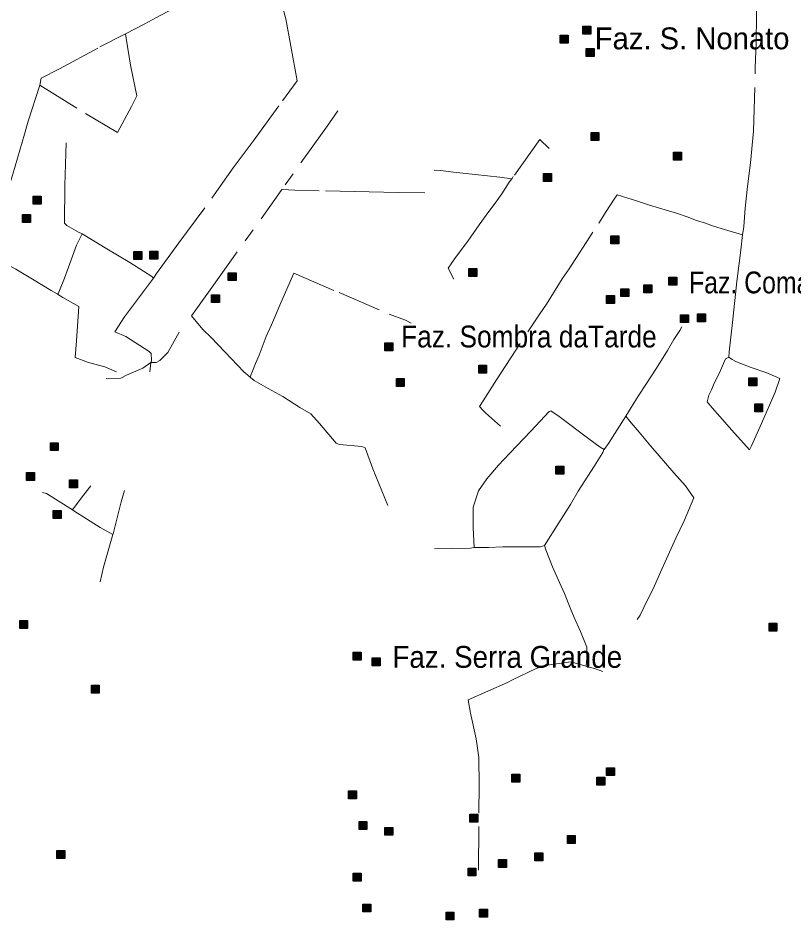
# Model space of a CAD drawing. Extents: x 393.5 to 446.9, y 8064.8 to 8120.4.
# Drawn here: x 419.31 to 425, y 8075.93 to 8082.54 of the extents above; entities that cross this region are included whole.
import ezdxf

# ---------------------------------------------------------------- set-up
doc = ezdxf.new("R2010")
doc.units = 0
doc.header["$LTSCALE"] = 0.064
doc.linetypes.add('DOT_DASHED', pattern=[7.7, 5, -1.2, 0.3, -1.2])
doc.layers.add('2', color=7, linetype='Continuous', lineweight=25)
doc.layers.add('22', color=7, linetype='DOT_DASHED', lineweight=13)
doc.layers.add('61', color=7, linetype='Continuous')

msp = doc.modelspace()

# ---------------------------------------------------------------- hatches: boundary and pattern name
at = {"layer": '2'}
for points in [[(423.4491, 8082.4828), (423.5071, 8082.4828), (423.5071, 8082.4248), (423.4491, 8082.4248)], [(423.2828, 8082.4172), (423.3408, 8082.4172), (423.3408, 8082.3592), (423.2828, 8082.3592)], [(423.473, 8082.319), (423.531, 8082.319), (423.531, 8082.261), (423.473, 8082.261)], [(423.5086, 8081.7029), (423.5666, 8081.7029), (423.5666, 8081.6449), (423.5086, 8081.6449)], [(424.1141, 8081.5584), (424.1721, 8081.5584), (424.1721, 8081.5004), (424.1141, 8081.5004)], [(423.1603, 8081.4031), (423.2183, 8081.4031), (423.2183, 8081.3451), (423.1603, 8081.3451)], [(419.4213, 8081.2362), (419.4793, 8081.2362), (419.4793, 8081.1782), (419.4213, 8081.1782)], [(419.3434, 8081.1027), (419.4014, 8081.1027), (419.4014, 8081.0447), (419.3434, 8081.0447)], [(423.6531, 8080.946), (423.7111, 8080.946), (423.7111, 8080.888), (423.6531, 8080.888)], [(420.1591, 8080.832), (420.2171, 8080.832), (420.2171, 8080.774), (420.1591, 8080.774)], [(420.2759, 8080.834), (420.3339, 8080.834), (420.3339, 8080.776), (420.2759, 8080.776)], [(420.8492, 8080.6762), (420.9072, 8080.6762), (420.9072, 8080.6182), (420.8492, 8080.6182)], [(422.6126, 8080.7057), (422.6706, 8080.7057), (422.6706, 8080.6477), (422.6126, 8080.6477)], [(424.0785, 8080.6427), (424.1365, 8080.6427), (424.1365, 8080.5847), (424.0785, 8080.5847)], [(423.728, 8080.5587), (423.786, 8080.5587), (423.786, 8080.5007), (423.728, 8080.5007)], [(423.8964, 8080.5861), (423.9544, 8080.5861), (423.9544, 8080.5281), (423.8964, 8080.5281)], [(420.7284, 8080.5146), (420.7864, 8080.5146), (420.7864, 8080.4566), (420.7284, 8080.4566)], [(423.6229, 8080.509), (423.6809, 8080.509), (423.6809, 8080.451), (423.6229, 8080.451)], [(424.1646, 8080.368), (424.2226, 8080.368), (424.2226, 8080.31), (424.1646, 8080.31)], [(424.2884, 8080.3752), (424.3464, 8080.3752), (424.3464, 8080.3172), (424.2884, 8080.3172)], [(421.9975, 8080.1619), (422.0555, 8080.1619), (422.0555, 8080.1039), (421.9975, 8080.1039)], [(422.6857, 8079.9989), (422.7437, 8079.9989), (422.7437, 8079.9409), (422.6857, 8079.9409)], [(422.0819, 8079.9007), (422.1399, 8079.9007), (422.1399, 8079.8427), (422.0819, 8079.8427)], [(424.6645, 8079.9048), (424.7225, 8079.9048), (424.7225, 8079.8468), (424.6645, 8079.8468)], [(424.708, 8079.7148), (424.766, 8079.7148), (424.766, 8079.6568), (424.708, 8079.6568)], [(419.5466, 8079.43), (419.6046, 8079.43), (419.6046, 8079.372), (419.5466, 8079.372)], [(419.3715, 8079.2122), (419.4295, 8079.2122), (419.4295, 8079.1542), (419.3715, 8079.1542)], [(423.2513, 8079.2582), (423.3093, 8079.2582), (423.3093, 8079.2002), (423.2513, 8079.2002)], [(419.6865, 8079.1571), (419.7445, 8079.1571), (419.7445, 8079.0991), (419.6865, 8079.0991)], [(419.5675, 8078.9326), (419.6255, 8078.9326), (419.6255, 8078.8746), (419.5675, 8078.8746)], [(419.3221, 8078.1269), (419.3801, 8078.1269), (419.3801, 8078.0689), (419.3221, 8078.0689)], [(424.813, 8078.1068), (424.871, 8078.1068), (424.871, 8078.0488), (424.813, 8078.0488)], [(421.7659, 8077.8952), (421.8239, 8077.8952), (421.8239, 8077.8372), (421.7659, 8077.8372)], [(421.9059, 8077.8528), (421.9639, 8077.8528), (421.9639, 8077.7948), (421.9059, 8077.7948)], [(419.847, 8077.6527), (419.905, 8077.6527), (419.905, 8077.5947), (419.847, 8077.5947)], [(423.6218, 8077.0484), (423.6798, 8077.0484), (423.6798, 8076.9904), (423.6218, 8076.9904)], [(422.9289, 8077.0014), (422.9869, 8077.0014), (422.9869, 8076.9434), (422.9289, 8076.9434)], [(423.5523, 8076.9787), (423.6103, 8076.9787), (423.6103, 8076.9207), (423.5523, 8076.9207)], [(421.7311, 8076.8792), (421.7891, 8076.8792), (421.7891, 8076.8212), (421.7311, 8076.8212)], [(422.6208, 8076.7077), (422.6788, 8076.7077), (422.6788, 8076.6497), (422.6208, 8076.6497)], [(421.8083, 8076.6545), (421.8663, 8076.6545), (421.8663, 8076.5965), (421.8083, 8076.5965)], [(421.9974, 8076.6116), (422.0554, 8076.6116), (422.0554, 8076.5536), (421.9974, 8076.5536)], [(423.3353, 8076.5509), (423.3933, 8076.5509), (423.3933, 8076.4929), (423.3353, 8076.4929)], [(419.5951, 8076.4417), (419.6531, 8076.4417), (419.6531, 8076.3837), (419.5951, 8076.3837)], [(422.8313, 8076.376), (422.8893, 8076.376), (422.8893, 8076.318), (422.8313, 8076.318)], [(423.0973, 8076.4243), (423.1553, 8076.4243), (423.1553, 8076.3663), (423.0973, 8076.3663)], [(422.6071, 8076.3136), (422.6651, 8076.3136), (422.6651, 8076.2556), (422.6071, 8076.2556)], [(421.7665, 8076.2747), (421.8245, 8076.2747), (421.8245, 8076.2167), (421.7665, 8076.2167)], [(421.8367, 8076.0496), (421.8947, 8076.0496), (421.8947, 8075.9916), (421.8367, 8075.9916)], [(422.4463, 8075.9909), (422.5043, 8075.9909), (422.5043, 8075.9329), (422.4463, 8075.9329)], [(422.6915, 8076.0111), (422.7495, 8076.0111), (422.7495, 8075.9531), (422.6915, 8075.9531)]]:
    msp.add_hatch(color=256, dxfattribs=at).paths.add_polyline_path(points)

# ---------------------------------------------------------------- linework, layer by layer
for points in [[(423.4491, 8082.4828), (423.5071, 8082.4828), (423.5071, 8082.4248), (423.4491, 8082.4248)], [(423.2828, 8082.4172), (423.3408, 8082.4172), (423.3408, 8082.3592), (423.2828, 8082.3592)], [(423.473, 8082.319), (423.531, 8082.319), (423.531, 8082.261), (423.473, 8082.261)], [(423.5086, 8081.7029), (423.5666, 8081.7029), (423.5666, 8081.6449), (423.5086, 8081.6449)], [(424.1141, 8081.5584), (424.1721, 8081.5584), (424.1721, 8081.5004), (424.1141, 8081.5004)], [(423.1603, 8081.4031), (423.2183, 8081.4031), (423.2183, 8081.3451), (423.1603, 8081.3451)], [(419.4213, 8081.2362), (419.4793, 8081.2362), (419.4793, 8081.1782), (419.4213, 8081.1782)], [(419.3434, 8081.1027), (419.4014, 8081.1027), (419.4014, 8081.0447), (419.3434, 8081.0447)], [(423.6531, 8080.946), (423.7111, 8080.946), (423.7111, 8080.888), (423.6531, 8080.888)], [(420.1591, 8080.832), (420.2171, 8080.832), (420.2171, 8080.774), (420.1591, 8080.774)], [(420.2759, 8080.834), (420.3339, 8080.834), (420.3339, 8080.776), (420.2759, 8080.776)], [(420.8492, 8080.6762), (420.9072, 8080.6762), (420.9072, 8080.6182), (420.8492, 8080.6182)], [(422.6126, 8080.7057), (422.6706, 8080.7057), (422.6706, 8080.6477), (422.6126, 8080.6477)], [(424.0785, 8080.6427), (424.1365, 8080.6427), (424.1365, 8080.5847), (424.0785, 8080.5847)], [(423.728, 8080.5587), (423.786, 8080.5587), (423.786, 8080.5007), (423.728, 8080.5007)], [(423.8964, 8080.5861), (423.9544, 8080.5861), (423.9544, 8080.5281), (423.8964, 8080.5281)], [(420.7284, 8080.5146), (420.7864, 8080.5146), (420.7864, 8080.4566), (420.7284, 8080.4566)], [(423.6229, 8080.509), (423.6809, 8080.509), (423.6809, 8080.451), (423.6229, 8080.451)], [(424.1646, 8080.368), (424.2226, 8080.368), (424.2226, 8080.31), (424.1646, 8080.31)], [(424.2884, 8080.3752), (424.3464, 8080.3752), (424.3464, 8080.3172), (424.2884, 8080.3172)], [(421.9975, 8080.1619), (422.0555, 8080.1619), (422.0555, 8080.1039), (421.9975, 8080.1039)], [(422.6857, 8079.9989), (422.7437, 8079.9989), (422.7437, 8079.9409), (422.6857, 8079.9409)], [(422.0819, 8079.9007), (422.1399, 8079.9007), (422.1399, 8079.8427), (422.0819, 8079.8427)], [(424.6645, 8079.9048), (424.7225, 8079.9048), (424.7225, 8079.8468), (424.6645, 8079.8468)], [(424.708, 8079.7148), (424.766, 8079.7148), (424.766, 8079.6568), (424.708, 8079.6568)], [(419.5466, 8079.43), (419.6046, 8079.43), (419.6046, 8079.372), (419.5466, 8079.372)], [(419.3715, 8079.2122), (419.4295, 8079.2122), (419.4295, 8079.1542), (419.3715, 8079.1542)], [(423.2513, 8079.2582), (423.3093, 8079.2582), (423.3093, 8079.2002), (423.2513, 8079.2002)], [(419.6865, 8079.1571), (419.7445, 8079.1571), (419.7445, 8079.0991), (419.6865, 8079.0991)], [(419.5675, 8078.9326), (419.6255, 8078.9326), (419.6255, 8078.8746), (419.5675, 8078.8746)], [(419.3221, 8078.1269), (419.3801, 8078.1269), (419.3801, 8078.0689), (419.3221, 8078.0689)], [(424.813, 8078.1068), (424.871, 8078.1068), (424.871, 8078.0488), (424.813, 8078.0488)], [(421.7659, 8077.8952), (421.8239, 8077.8952), (421.8239, 8077.8372), (421.7659, 8077.8372)], [(421.9059, 8077.8528), (421.9639, 8077.8528), (421.9639, 8077.7948), (421.9059, 8077.7948)], [(419.847, 8077.6527), (419.905, 8077.6527), (419.905, 8077.5947), (419.847, 8077.5947)], [(423.6218, 8077.0484), (423.6798, 8077.0484), (423.6798, 8076.9904), (423.6218, 8076.9904)], [(422.9289, 8077.0014), (422.9869, 8077.0014), (422.9869, 8076.9434), (422.9289, 8076.9434)], [(423.5523, 8076.9787), (423.6103, 8076.9787), (423.6103, 8076.9207), (423.5523, 8076.9207)], [(421.7311, 8076.8792), (421.7891, 8076.8792), (421.7891, 8076.8212), (421.7311, 8076.8212)], [(422.6208, 8076.7077), (422.6788, 8076.7077), (422.6788, 8076.6497), (422.6208, 8076.6497)], [(421.8083, 8076.6545), (421.8663, 8076.6545), (421.8663, 8076.5965), (421.8083, 8076.5965)], [(421.9974, 8076.6116), (422.0554, 8076.6116), (422.0554, 8076.5536), (421.9974, 8076.5536)], [(423.3353, 8076.5509), (423.3933, 8076.5509), (423.3933, 8076.4929), (423.3353, 8076.4929)], [(419.5951, 8076.4417), (419.6531, 8076.4417), (419.6531, 8076.3837), (419.5951, 8076.3837)], [(422.8313, 8076.376), (422.8893, 8076.376), (422.8893, 8076.318), (422.8313, 8076.318)], [(423.0973, 8076.4243), (423.1553, 8076.4243), (423.1553, 8076.3663), (423.0973, 8076.3663)], [(422.6071, 8076.3136), (422.6651, 8076.3136), (422.6651, 8076.2556), (422.6071, 8076.2556)], [(421.7665, 8076.2747), (421.8245, 8076.2747), (421.8245, 8076.2167), (421.7665, 8076.2167)], [(421.8367, 8076.0496), (421.8947, 8076.0496), (421.8947, 8075.9916), (421.8367, 8075.9916)], [(422.4463, 8075.9909), (422.5043, 8075.9909), (422.5043, 8075.9329), (422.4463, 8075.9329)], [(422.6915, 8076.0111), (422.7495, 8076.0111), (422.7495, 8075.9531), (422.6915, 8075.9531)]]:
    msp.add_lwpolyline(points, close=True, dxfattribs=at)
at = {"layer": '22'}
for p, q in [((420.3065, 8080.6436), (420.3015, 8080.6367)), ((424.5187, 8080.0569), (424.5194, 8080.0564)), ((420.0066, 8078.7636), (420.0051, 8078.7584))]:
    msp.add_line(p, q, dxfattribs=at)
for points in [[(420.3065, 8080.6436), (420.3252, 8080.6691), (420.4891, 8080.8947), (420.7309, 8081.2224), (420.8857, 8081.4438), (421.0319, 8081.6405), (421.2485, 8081.9354), (421.3543, 8082.0817), (421.3088, 8082.3367), (421.2712, 8082.5361), (421.2431, 8082.6437), (421.2067, 8082.8588), (421.1904, 8082.9751), (421.1774, 8082.9951)], [(420.0973, 8082.4264), (420.2394, 8082.499), (420.319, 8082.5441), (420.4442, 8082.6109)], [(424.619, 8080.9541), (424.6272, 8081.0146), (424.6383, 8081.1482), (424.6561, 8081.3076), (424.6761, 8081.48), (424.6997, 8081.7129), (424.7115, 8082.1783), (424.7182, 8082.3615), (424.7204, 8082.5619), (424.7204, 8082.6179)], [(419.4698, 8082.0501), (419.8035, 8081.8431), (420.0393, 8081.7034), (420.1414, 8081.8935), (420.1793, 8081.9723), (420.1329, 8082.1971), (420.1009, 8082.3958), (420.0973, 8082.4264)], [(419.4698, 8082.0501), (419.47, 8082.0507), (419.4786, 8082.1028), (419.6134, 8082.1707), (419.9094, 8082.3302), (420.0973, 8082.4264)], [(419.218, 8081.2277), (419.272, 8081.3983), (419.3572, 8081.6906), (419.3849, 8081.786), (419.4698, 8082.0501)], [(421.6543, 8081.8631), (421.569, 8081.7421), (421.2429, 8081.2849)], [(423.201, 8081.586), (423.1329, 8081.6521), (422.9391, 8081.3799), (422.9303, 8081.3662), (422.93, 8081.3657), (422.9288, 8081.3639)], [(419.6629, 8081.6281), (419.6535, 8081.3147), (419.6507, 8081.0394), (419.667, 8081.0231), (419.7525, 8080.9729), (419.7796, 8080.9621)], [(422.3596, 8081.4279), (422.4049, 8081.4259), (422.4998, 8081.4139), (422.6586, 8081.3959), (422.8401, 8081.3759), (422.9287, 8081.3639), (422.9288, 8081.3639)], [(422.9288, 8081.3639), (422.9084, 8081.3384), (422.8548, 8081.2544), (422.8053, 8081.1863), (422.7599, 8081.1243), (422.6898, 8081.0262), (422.6052, 8080.9082), (422.5165, 8080.7881), (422.4609, 8080.7081), (422.5021, 8080.6285)], [(420.5801, 8080.3591), (420.612, 8080.4046), (420.7294, 8080.5677), (421.2215, 8081.2542), (421.2429, 8081.2849)], [(422.291, 8081.2602), (422.0962, 8081.2644), (421.8818, 8081.2687), (421.5165, 8081.2772), (421.3374, 8081.2797), (421.2459, 8081.2847), (421.2429, 8081.2849)], [(422.8463, 8079.5525), (422.736, 8079.6493), (422.715, 8079.6697), (422.6922, 8079.6952), (422.7185, 8079.7377), (422.8148, 8079.8906), (423.0983, 8080.3225), (423.1333, 8080.3735), (423.1823, 8080.4466), (423.2979, 8080.6301), (423.3487, 8080.7048), (423.5651, 8081.0385), (423.6194, 8081.1235), (423.6772, 8081.2152), (423.7, 8081.2458), (423.8418, 8081.2033), (423.9381, 8081.1711), (424.1413, 8081.1096), (424.2131, 8081.0859), (424.2817, 8081.0593), (424.3474, 8081.0386), (424.4069, 8081.0178), (424.4863, 8080.9926), (424.5351, 8080.9778), (424.5931, 8080.9615), (424.619, 8080.9541)], [(419.6047, 8080.521), (419.6138, 8080.5463), (419.6509, 8080.6352), (419.7388, 8080.8779), (419.7769, 8080.9566), (419.7788, 8080.9605), (419.7796, 8080.9621)], [(419.7796, 8080.9621), (419.8488, 8080.9187), (419.9492, 8080.8577), (420.1284, 8080.7519), (420.2302, 8080.6868), (420.2905, 8080.6477), (420.3015, 8080.6367)], [(424.619, 8080.9541), (424.6053, 8080.8423), (424.5773, 8080.6105), (424.5455, 8080.3114), (424.5214, 8080.097), (424.5187, 8080.0569)], [(419.1524, 8080.7874), (419.2086, 8080.7474), (419.2941, 8080.7013), (419.4149, 8080.6294), (419.5534, 8080.5467), (419.5967, 8080.5212), (419.5993, 8080.5197)], [(421.0099, 8079.9099), (421.0161, 8079.9251), (421.0271, 8079.9555), (421.049, 8080.0117), (421.0756, 8080.0724), (421.1273, 8080.2076), (421.1679, 8080.2942), (421.2354, 8080.4563), (421.3303, 8080.6723), (421.6617, 8080.5299), (422.0286, 8080.3724), (422.1496, 8080.3271), (422.1903, 8080.3074)], [(420.3015, 8080.6367), (420.2218, 8080.528), (420.0909, 8080.3517), (420.018, 8080.2428), (420.0994, 8080.2076), (420.2718, 8080.0991), (420.2854, 8080.0828), (420.2867, 8080.0353), (420.2843, 8080.0189)], [(419.5993, 8080.5197), (419.6373, 8080.4953), (419.7554, 8080.4275), (419.7381, 8080.1759), (419.7277, 8080.0556), (419.8271, 8080.0177), (419.9452, 8079.9852), (420.0307, 8079.9499)], [(420.5801, 8080.3591), (420.6645, 8080.2587), (420.7258, 8080.2014), (420.8252, 8080.0967), (420.8722, 8080.0466), (420.9645, 8079.9494), (421.0099, 8079.9099)], [(423.7648, 8079.6251), (423.8531, 8079.7716), (423.9156, 8079.8651), (423.9888, 8079.9777), (424.0691, 8080.1059), (424.1156, 8080.1874), (424.1602, 8080.2515), (424.1745, 8080.2792)], [(420.2825, 8080.0181), (420.322, 8080.0172), (420.3491, 8080.0322), (420.4062, 8080.0918), (420.455, 8080.1745), (420.4669, 8080.1965), (420.4903, 8080.241)], [(420.2825, 8080.0181), (420.2231, 8079.9757), (420.1037, 8079.9242), (420.063, 8079.9038), (419.9558, 8079.9011)], [(420.2825, 8080.0181), (420.2818, 8080.0147), (420.2745, 8079.9499)], [(424.5194, 8080.0564), (424.5428, 8080.0392), (424.5748, 8080.023), (424.6817, 8079.9815), (424.7961, 8079.943), (424.8923, 8079.9008), (424.8587, 8079.8016), (424.7566, 8079.5714), (424.6848, 8079.407), (424.6696, 8079.3774), (424.5398, 8079.5232), (424.4513, 8079.6225), (424.3963, 8079.6847), (424.3588, 8079.7292), (424.3713, 8079.7778), (424.3909, 8079.8167)], [(424.3909, 8079.8167), (424.3918, 8079.8187), (424.4101, 8079.8661), (424.4498, 8079.9431), (424.4941, 8080.0438), (424.5187, 8080.0569)], [(422.0186, 8078.9713), (421.9092, 8079.2388), (421.8523, 8079.3938), (421.8282, 8079.4013), (421.6663, 8079.4161), (421.64, 8079.4268), (421.5197, 8079.5711), (421.4541, 8079.6412), (421.3753, 8079.6879), (421.2506, 8079.7697), (421.1434, 8079.827), (421.0406, 8079.8864), (421.0126, 8079.9078), (421.0108, 8079.9092), (421.0099, 8079.9099)], [(422.6532, 8078.6612), (422.6448, 8078.8072), (422.6448, 8078.9579), (422.685, 8079.0783), (422.7439, 8079.1666), (422.8296, 8079.2654), (422.9135, 8079.3538), (423.068, 8079.5157), (423.1358, 8079.5885), (423.2019, 8079.6578), (423.2144, 8079.6647), (423.2751, 8079.6214), (423.492, 8079.4577), (423.5759, 8079.3987), (423.6038, 8079.3797)], [(423.7648, 8079.6251), (423.6362, 8079.4241), (423.6038, 8079.3797)], [(423.847, 8078.1338), (423.8697, 8078.1664), (423.8947, 8078.2218), (423.9732, 8078.3812), (424.0268, 8078.5025), (424.1312, 8078.7303), (424.1902, 8078.8568), (424.2624, 8079.0275), (424.2017, 8079.1141), (424.1142, 8079.2094), (423.9473, 8079.4061), (423.8616, 8079.5066), (423.8035, 8079.5768), (423.7648, 8079.6251)], [(423.1674, 8078.6768), (423.2735, 8078.8426), (423.3574, 8078.9778), (423.4145, 8079.0748), (423.486, 8079.184), (423.5342, 8079.2602), (423.5949, 8079.359), (423.6036, 8079.3793), (423.6038, 8079.3797)], [(419.7079, 8078.9389), (419.7786, 8079.0332), (419.843, 8079.1132)], [(420.0066, 8078.7636), (420.0648, 8078.9978), (420.0887, 8079.0802)], [(419.7079, 8078.9389), (419.5185, 8079.0582), (419.4892, 8079.0655)], [(419.7079, 8078.9389), (419.7195, 8078.9322), (419.9108, 8078.8091), (420.0051, 8078.7584)], [(420.0051, 8078.7584), (419.9368, 8078.5171), (419.9114, 8078.4111)], [(422.6532, 8078.6612), (422.7568, 8078.6629), (422.8621, 8078.6664), (423.1353, 8078.6681), (423.1674, 8078.6768)], [(423.1674, 8078.6768), (423.1772, 8078.6448), (423.2272, 8078.5218), (423.2781, 8078.4066), (423.3138, 8078.3251), (423.356, 8078.2206)], [(422.3604, 8078.6525), (422.6246, 8078.6577), (422.6532, 8078.6612)], [(423.356, 8078.2206), (423.3855, 8078.1488), (423.4312, 8078.0466), (423.4769, 8077.9329), (423.4789, 8077.8499), (423.4729, 8077.7921)], [(422.6849, 8076.2966), (422.6869, 8076.717), (422.6888, 8076.9156), (422.6869, 8077.1224), (422.667, 8077.2593), (422.6252, 8077.4483), (422.6094, 8077.5467), (422.8955, 8077.6739), (422.9343, 8077.6931), (423.1073, 8077.7747), (423.1709, 8077.7979), (423.3617, 8077.8249), (423.4729, 8077.7921), (423.4779, 8077.7907)], [(423.4779, 8077.7907), (423.5405, 8077.7728), (423.5961, 8077.7535)]]:
    msp.add_lwpolyline(points, dxfattribs=at)

# ---------------------------------------------------------------- texts
at = {"layer": '61'}
msp.add_text('Faz. S. Nonato', height=0.16, dxfattribs=at).set_placement((423.5356, 8082.3133))
for s, width, p in [('Faz. Comancha', 0.85, (424.2267, 8080.5246)), ('Faz. Sombra daTarde', 0.9, (422.1168, 8080.1284)), ('Faz. Serra Grande', 0.95, (422.0534, 8077.7807))]:
    msp.add_text(s, height=0.16, dxfattribs=dict(at, width=width)).set_placement(p)

doc.saveas('drawing.dxf')
